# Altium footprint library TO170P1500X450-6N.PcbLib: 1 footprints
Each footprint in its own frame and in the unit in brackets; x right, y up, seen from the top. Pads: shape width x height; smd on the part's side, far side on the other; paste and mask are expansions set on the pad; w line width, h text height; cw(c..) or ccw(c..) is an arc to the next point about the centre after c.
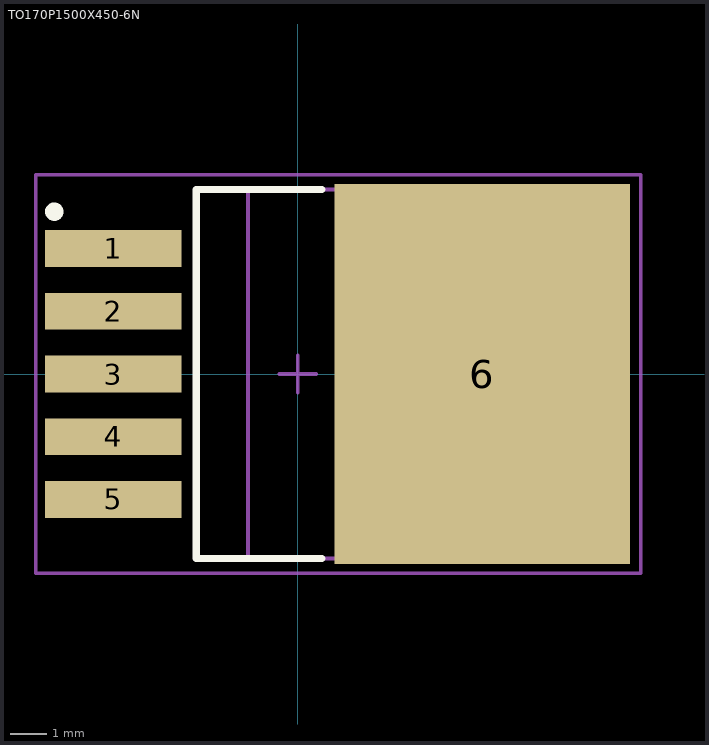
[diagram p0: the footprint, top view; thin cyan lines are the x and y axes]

## TO170P1500X450-6N [mm] "TO,1.70mm pitch;5 pin,15.00mm L X 9.25mm W X 4.50mm H body"
height 4.5
pads (6):
  rect 3.7x1 smd paste+0 mask+0: 1(-5,3.4) 2(-5,1.7) 3(-5,0) 4(-5,-1.7) 5(-5,-3.4)
  rect 8x10.3 smd paste+0 mask+0: 6(5,0)
Top Overlay:
  circle w0.25: c-6.6,4.4 r0.125
  lines w0.2: 0.65,-5 -2.75,-5 -2.75,5 0.65,5
M3 (ASY_Text_Top):
  text ".DESIGNATOR" at 0,0 h1.2
M13 (CMP_Body_OTL_Top):
  lines w0.1: -1.35,-5 7.9,-5 7.9,5 -1.35,5 -1.35,-5
M15 (CMP_Courtyard_Top):
  lines w0.1: -0.5,0 0.5,0 ; 0,-0.5 0,0.5 ; -7.1,-5.4 9.3,-5.4 9.3,5.4 -7.1,5.4 -7.1,-5.4
3D body "PG-TO263-5.stp": height 4.51, standoff 0, extent -6.4,-5 8.55,5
